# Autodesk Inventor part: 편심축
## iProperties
Manager: 한국ATC센터
Company: 한국ATC센터
Created: 2014-10
Part Number: 편심축
Document SubType Name: Modeling
Designer: 한국ATC센터
Density: 7.86 g/cm^3
Material: 강, 연강
Mass: 1140.06 g
Surface Area: 226.679 cm^2
Volume: 145.046 cm^3
Author: KYOUNG IL JANG
